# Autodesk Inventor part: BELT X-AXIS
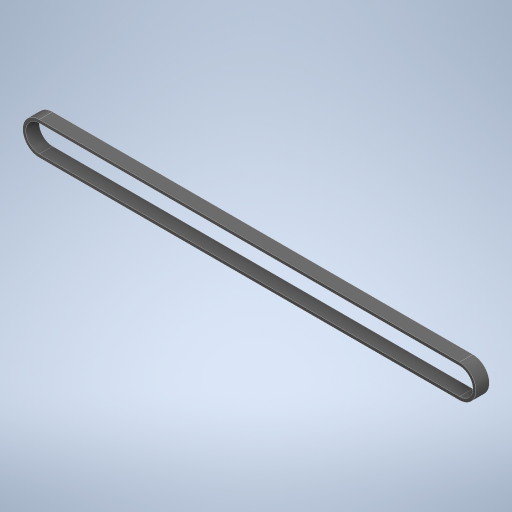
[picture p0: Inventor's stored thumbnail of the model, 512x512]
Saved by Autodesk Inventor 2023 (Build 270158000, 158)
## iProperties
Created: 2025-07
Part Number: BELT X-AXIS
Material: Generic
Document SubType Name: Modeling
Designer: erjon
Density: 1 g/cm^3
Appearance: Default
Author: erjon
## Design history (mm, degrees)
feature "Base1"
body "Solid1"
